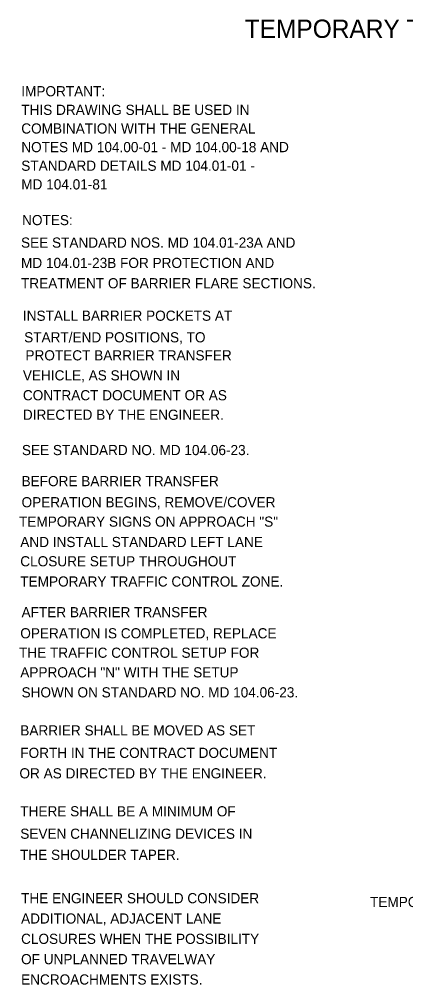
# Model space of a CAD drawing. Extents: x 1531.4 to 1538.6, y 1529.6 to 1539.6.
# Drawn here: x 1531.41 to 1533.69, y 1533.9 to 1539.6 of the extents above; entities that cross this region are included whole.
import ezdxf

# ---------------------------------------------------------------- set-up
doc = ezdxf.new("R2010")
doc.units = 0
doc.layers.add('DETL-NOTE', color=7, linetype='Continuous')
doc.layers.add('DETL-TITL', color=7, linetype='Continuous')

msp = doc.modelspace()

# ---------------------------------------------------------------- texts
at = {"layer": 'DETL-NOTE'}
for s, p in [('IMPORTANT:', (1531.4243, 1539.1423)), ('THIS DRAWING SHALL BE USED IN', (1531.4243, 1539.0323)), ('COMBINATION WITH THE GENERAL', (1531.4243, 1538.9223)), ('NOTES MD 104.00-01 - MD 104.00-18 AND', (1531.4243, 1538.8123)), ('STANDARD DETAILS MD 104.01-01 -', (1531.4243, 1538.7023)), ('MD 104.01-81', (1531.4243, 1538.5923)), ('NOTES:', (1531.4292, 1538.3813)), ('SEE STANDARD NOS. MD 104.01-23A AND ', (1531.4228, 1538.2483)), ('MD 104.01-23B FOR PROTECTION AND ', (1531.4228, 1538.1283)), ('TREATMENT OF BARRIER FLARE SECTIONS. ', (1531.4228, 1538.0083)), ('INSTALL BARRIER POCKETS AT', (1531.4338, 1537.8166)), ('START/END POSITIONS, TO', (1531.4413, 1537.6891)), ('PROTECT BARRIER TRANSFER', (1531.4488, 1537.5826)), ('VEHICLE, AS SHOWN IN', (1531.4338, 1537.4644)), ('CONTRACT DOCUMENT OR AS', (1531.4338, 1537.347)), ('DIRECTED BY THE ENGINEER.', (1531.4338, 1537.2317)), ('SEE STANDARD NO. MD 104.06-23.', (1531.428, 1537.0232)), ('BEFORE BARRIER TRANSFER', (1531.426, 1536.8398)), ('OPERATION BEGINS, REMOVE/COVER', (1531.426, 1536.7152)), ('TEMPORARY SIGNS ON APPROACH "S"', (1531.411, 1536.6006)), ('AND INSTALL STANDARD LEFT LANE', (1531.4185, 1536.4803)), ('CLOSURE SETUP THROUGHOUT ', (1531.4185, 1536.3665)), ('TEMPORARY TRAFFIC CONTROL ZONE.', (1531.4185, 1536.2471)), ('AFTER BARRIER TRANSFER ', (1531.426, 1536.0658)), ('OPERATION IS COMPLETED, REPLACE', (1531.4185, 1535.9412)), ('THE TRAFFIC CONTROL SETUP FOR', (1531.411, 1535.8265)), ('APPROACH "N" WITH THE SETUP', (1531.4185, 1535.7106)), ('SHOWN ON STANDARD NO. MD 104.06-23.', (1531.426, 1535.5925)), ('BARRIER SHALL BE MOVED AS SET ', (1531.4185, 1535.3677)), ('FORTH IN THE CONTRACT DOCUMENT', (1531.4185, 1535.2352)), ('OR AS DIRECTED BY THE ENGINEER.', (1531.4136, 1535.1143)), ('THERE SHALL BE A MINIMUM OF', (1531.4185, 1534.8901)), ('SEVEN CHANNELIZING DEVICES IN', (1531.4185, 1534.7576)), ('THE SHOULDER TAPER.', (1531.4172, 1534.6331)), ('THE ENGINEER SHOULD CONSIDER', (1531.4232, 1534.3769)), ('TEMPORARY STRIPING (TYP.)', (1533.4817, 1534.3543)), ('ADDITIONAL, ADJACENT LANE', (1531.4232, 1534.2569)), ('CLOSURES WHEN THE POSSIBILITY', (1531.4232, 1534.1369)), ('OF UNPLANNED TRAVELWAY', (1531.4232, 1534.0169)), ('ENCROACHMENTS EXISTS.', (1531.4232, 1533.8969))]:
    msp.add_text(s, height=0.06, dxfattribs=at).set_placement(p)
at = {"layer": 'DETL-TITL'}
msp.add_text('TEMPORARY TRAFFIC CONTROL TYPICAL APPLICATION', height=0.108, dxfattribs=at).set_placement((1532.7424, 1539.4873))

doc.saveas('drawing.dxf')
